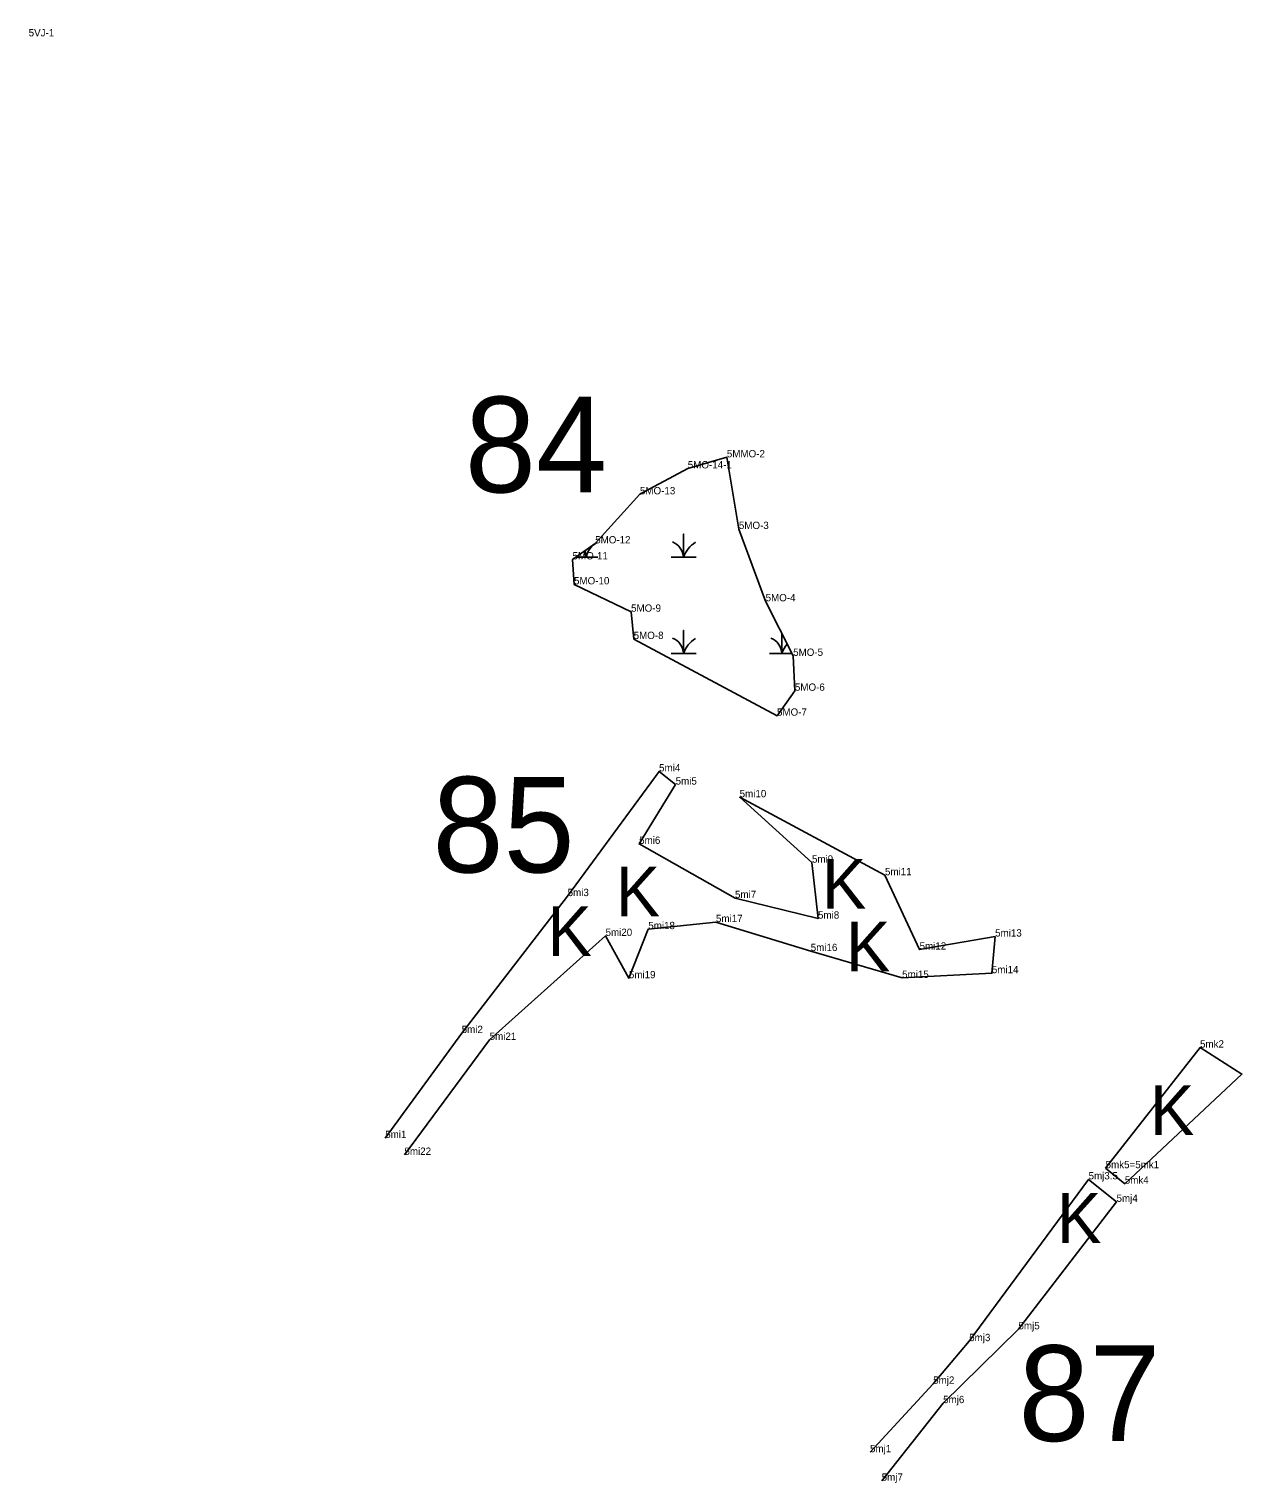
# Model space of a CAD drawing. Extents: x 2072529 to 2268796, y 436423 to 470406.
# Drawn here: x 2129755 to 2130584, y 446158 to 447153 of the extents above; entities that cross this region are included whole.
import ezdxf

# ---------------------------------------------------------------- set-up
doc = ezdxf.new("R2010")
doc.units = 0
for name, color, linetype in [('Default', 7, 'Continuous'), ('Exist Environmental Wetland Boundary Cogo Comment', 7, 'Continuous'), ('Exist Environmental Wetland Boundary Cogo Point CELL', 7, 'Continuous'), ('Old_Level_20', 7, 'Continuous')]:
    doc.layers.add(name, color=color, linetype=linetype)

msp = doc.modelspace()

# ---------------------------------------------------------------- linework, layer by layer
at = {"layer": 'Exist Environmental Wetland Boundary Cogo Point CELL'}
for points in [[(2130193.82, 446791.33), (2130202.42, 446791.33), (2130202.42, 446807.11), (2130202.42, 446791.33), (2130211.03, 446791.33)], [(2130128.57, 446791.33), (2130135.17, 446791.33), (2130135.17, 446796)], [(2130135.17, 446796), (2130135.17, 446791.33), (2130143.78, 446791.33)], [(2130193.82, 446725.53), (2130202.42, 446725.53), (2130202.42, 446741.31), (2130202.42, 446725.53), (2130211.03, 446725.53)], [(2130261.07, 446725.53), (2130269.67, 446725.53), (2130269.67, 446739.05)], [(2130269.67, 446739.05), (2130269.67, 446725.53), (2130276.49, 446725.53)]]:
    msp.add_lwpolyline(points, dxfattribs=at)
for centre, radius, start, end in [((2130153.42, 446785.27), 19.22, 122.12745, 161.62219), ((2130190.16, 446790.44), 12.3, 4.14034, 67.53497), ((2130220.67, 446785.27), 19.22, 122.12745, 161.62219), ((2130122.91, 446790.44), 12.3, 4.14034, 23.32416), ((2130190.16, 446724.64), 12.3, 4.14034, 67.53497), ((2130220.67, 446719.47), 19.22, 122.12745, 161.62219), ((2130257.41, 446724.64), 12.3, 4.14034, 67.53497), ((2130287.92, 446719.47), 19.22, 139.63793, 161.62219)]:
    msp.add_arc(centre, radius, start, end, dxfattribs=at)
at = {"layer": 'Old_Level_20'}
for p, q in [((2130232.01, 446859.66), (2130232.01, 446859.66)), ((2130205.28, 446852.08), (2130205.28, 446852.08)), ((2130172.57, 446834.36), (2130172.57, 446834.36)), ((2130240.22, 446810.63), (2130240.22, 446810.63)), ((2130141.95, 446800.79), (2130141.95, 446800.79)), ((2130126.47, 446789.84), (2130126.47, 446789.84)), ((2130127.49, 446772.77), (2130127.49, 446772.77)), ((2130258.5, 446761.21), (2130258.5, 446761.21)), ((2130166.5, 446754.07), (2130166.5, 446754.07)), ((2130168.29, 446735.39), (2130168.29, 446735.39)), ((2130277.33, 446723.87), (2130277.33, 446723.87)), ((2130278.53, 446700), (2130278.53, 446700)), ((2130266.29, 446682.95), (2130266.29, 446682.95)), ((2130185.65, 446644.86), (2130185.65, 446644.86)), ((2130196.98, 446635.85), (2130196.98, 446635.85)), ((2130240.76, 446627.17), (2130240.76, 446627.17)), ((2130172.02, 446595.3), (2130172.02, 446595.3)), ((2130290.21, 446582.45), (2130290.21, 446582.45)), ((2130340.13, 446573.85), (2130340.13, 446573.85)), ((2130123.11, 446559.57), (2130123.11, 446559.57)), ((2130237.57, 446558.23), (2130237.57, 446558.23)), ((2130224.55, 446541.78), (2130224.55, 446541.78)), ((2130294.34, 446544.16), (2130294.34, 446544.16)), ((2130149.04, 446532.32), (2130149.04, 446532.32)), ((2130178.27, 446536.97), (2130178.27, 446536.97)), ((2130415.44, 446531.92), (2130415.44, 446531.92)), ((2130289.35, 446521.99), (2130289.35, 446521.99)), ((2130363.78, 446522.98), (2130363.78, 446522.98)), ((2130165, 446503.38), (2130165, 446503.38)), ((2130351.84, 446503.6), (2130351.84, 446503.6)), ((2130413.21, 446506.86), (2130413.21, 446506.86)), ((2130050.66, 446465.93), (2130050.66, 446465.93)), ((2130069.78, 446461.25), (2130069.78, 446461.25)), ((2130555.58, 446455.99), (2130555.58, 446455.99)), ((2130584.22, 446437.87), (2130584.22, 446437.87)), ((2129998.37, 446394.12), (2129998.37, 446394.12)), ((2130011.52, 446382.62), (2130011.52, 446382.62)), ((2130491, 446373.48), (2130491, 446373.48)), ((2130479.36, 446365.84), (2130479.36, 446365.84)), ((2130504.14, 446362.9), (2130504.14, 446362.9)), ((2130498.48, 446350.48), (2130498.48, 446350.48)), ((2130431.42, 446263.3), (2130431.42, 446263.3)), ((2130397.71, 446255.21), (2130397.71, 446255.21)), ((2130373.09, 446226.07), (2130373.09, 446226.07)), ((2130379.9, 446212.81), (2130379.9, 446212.81)), ((2130329.92, 446179.25), (2130329.92, 446179.25)), ((2130337.88, 446159.75), (2130337.88, 446159.75))]:
    msp.add_line(p, q, dxfattribs=at)
for points in [[(2130205.28, 446852.08), (2130232.01, 446859.66), (2130240.22, 446810.63), (2130258.5, 446761.21), (2130277.33, 446723.87), (2130278.53, 446700), (2130266.29, 446682.95), (2130168.29, 446735.39), (2130166.5, 446754.07), (2130127.49, 446772.77), (2130126.47, 446789.84), (2130141.95, 446800.79), (2130172.57, 446834.36)], [(2130491, 446373.48), (2130555.58, 446455.99), (2130584.22, 446437.87), (2130504.14, 446362.9)]]:
    msp.add_lwpolyline(points, close=True, dxfattribs=at)
for points in [[(2129998.37, 446394.12), (2130050.66, 446465.93), (2130123.11, 446559.57), (2130185.65, 446644.86), (2130196.98, 446635.85), (2130172.02, 446595.3), (2130237.57, 446558.23), (2130294.34, 446544.16), (2130290.21, 446582.45), (2130240.76, 446627.17), (2130340.13, 446573.85), (2130363.78, 446522.98), (2130415.44, 446531.92), (2130413.21, 446506.86), (2130351.84, 446503.6), (2130289.35, 446521.99), (2130224.55, 446541.78), (2130178.27, 446536.97), (2130165, 446503.38), (2130149.04, 446532.32), (2130069.78, 446461.25), (2130011.52, 446382.62)], [(2130329.92, 446179.25), (2130373.09, 446226.07), (2130397.71, 446255.21), (2130479.36, 446365.84), (2130498.48, 446350.48), (2130431.42, 446263.3), (2130379.9, 446212.81), (2130337.88, 446159.75)]]:
    msp.add_lwpolyline(points, dxfattribs=at)

# ---------------------------------------------------------------- texts
at = {"layer": 'Default'}
for s, p in [('84', (2130052.83, 446835.71)), ('85', (2130030.69, 446575.78)), ('87', (2130431.41, 446186.92))]:
    msp.add_text(s, height=65.34, dxfattribs=at).set_placement(p)
at = {"layer": 'Exist Environmental Wetland Boundary Cogo Comment'}
for s, p in [('5VJ-1', (2129754.55, 447147.54)), ('5MO-14-1', (2130205.28, 446852.08)), ('5MMO-2', (2130232.01, 446859.66)), ('5MO-13', (2130172.57, 446834.36)), ('5MO-3', (2130240.22, 446810.63)), ('5MO-12', (2130141.95, 446800.79)), ('5MO-11', (2130126.47, 446789.84)), ('5MO-10', (2130127.49, 446772.77)), ('5MO-9', (2130166.5, 446754.07)), ('5MO-4', (2130258.5, 446761.21)), ('5MO-8', (2130168.29, 446735.39)), ('5MO-5', (2130277.33, 446723.87)), ('5MO-6', (2130278.53, 446700)), ('5MO-7', (2130266.29, 446682.95)), ('5mi4', (2130185.65, 446644.86)), ('5mi5', (2130196.98, 446635.85)), ('5mi10', (2130240.76, 446627.17)), ('5mi6', (2130172.02, 446595.3)), ('5mi9', (2130290.21, 446582.45)), ('5mi11', (2130340.13, 446573.85)), ('5mi3', (2130123.11, 446559.57)), ('5mi7', (2130237.57, 446558.23)), ('5mi8', (2130294.34, 446544.16)), ('5mi18', (2130178.27, 446536.97)), ('5mi17', (2130224.55, 446541.78)), ('5mi20', (2130149.04, 446532.32)), ('5mi13', (2130415.44, 446531.92)), ('5mi16', (2130289.35, 446521.99)), ('5mi12', (2130363.78, 446522.98)), ('5mi14', (2130413.21, 446506.86)), ('5mi19', (2130165, 446503.38)), ('5mi15', (2130351.84, 446503.6)), ('5mi2', (2130050.66, 446465.93)), ('5mi21', (2130069.78, 446461.25)), ('5mk2', (2130555.58, 446455.99)), ('5mi1', (2129998.37, 446394.12)), ('5mi22', (2130011.52, 446382.62)), ('5mj3.5', (2130479.36, 446365.84)), ('5mk5=5mk1', (2130491, 446373.48)), ('5mk4', (2130504.14, 446362.9)), ('5mj4', (2130498.48, 446350.48)), ('5mj3', (2130397.71, 446255.21)), ('5mj5', (2130431.42, 446263.3)), ('5mj2', (2130373.09, 446226.07)), ('5mj6', (2130379.9, 446212.81)), ('5mj1', (2130329.92, 446179.25)), ('5mj7', (2130337.88, 446159.75))]:
    msp.add_text(s, height=5, dxfattribs=at).set_placement(p)
at = {"layer": 'Exist Environmental Wetland Boundary Cogo Point CELL'}
for p in [(2130155.99, 446545.67), (2130297.04, 446550.98), (2130109.33, 446518.63), (2130313.48, 446508.02), (2130521.35, 446396.14), (2130457.71, 446322.43)]:
    msp.add_text('K', height=34, dxfattribs=at).set_placement(p)

doc.saveas('drawing.dxf')
